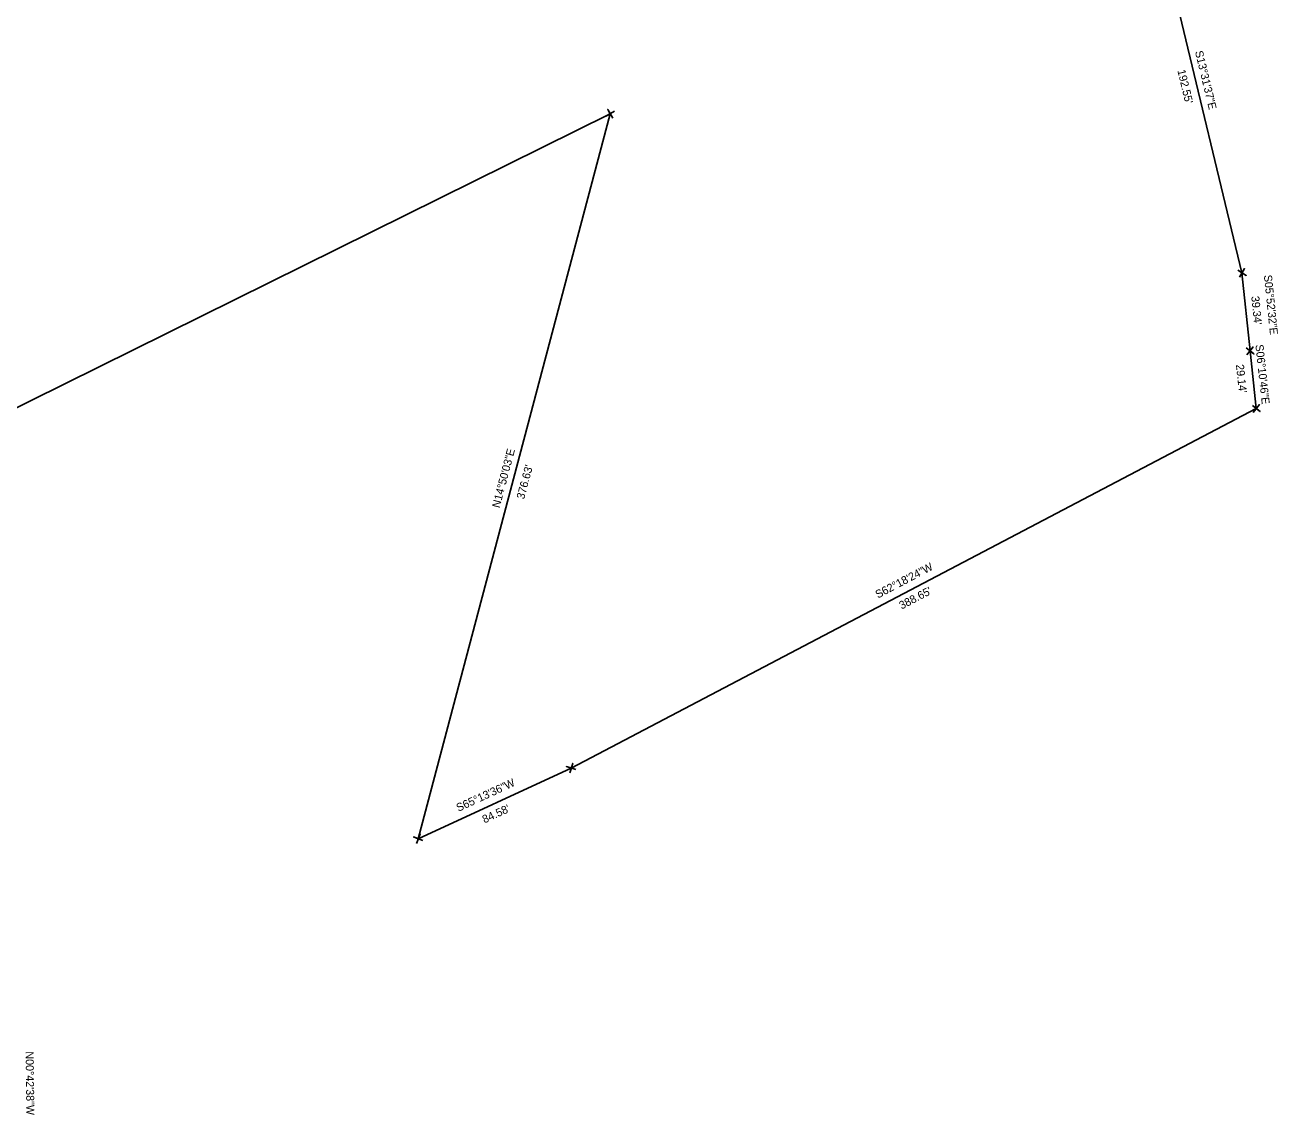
# Model space of a CAD drawing. Extents: x 1107874 to 1110849, y 645477 to 647181.
# Drawn here: x 1110220 to 1110849, y 646136 to 646683 of the extents above; entities that cross this region are included whole.
import ezdxf

# ---------------------------------------------------------------- set-up
doc = ezdxf.new("R2010")
doc.units = 0
for name, color, linetype in [('Exist Property Corner CELL', 7, 'Continuous'), ('Exist Property Line', 7, 'Continuous'), ('Exist Property Text', 7, 'Continuous')]:
    doc.layers.add(name, color=color, linetype=linetype)

msp = doc.modelspace()

# ---------------------------------------------------------------- linework, layer by layer
at = {"layer": 'Exist Property Corner CELL'}
for p, q in [((1110513.95, 646638.85), (1110513.95, 646638.85)), ((1110831.29, 646558.94), (1110831.29, 646558.94)), ((1110835.32, 646519.8), (1110835.32, 646519.8)), ((1110838.45, 646490.83), (1110838.45, 646490.83)), ((1110494.32, 646310.21), (1110494.32, 646310.21)), ((1110417.53, 646274.77), (1110417.53, 646274.77))]:
    msp.add_line(p, q, dxfattribs=at)
for points in [[(1110515.21, 646636.69), (1110512.7, 646641.01), (1110513.95, 646638.85), (1110511.79, 646637.59), (1110516.12, 646640.1)], [(1110829.16, 646560.24), (1110833.42, 646557.63), (1110831.29, 646558.94), (1110832.59, 646561.07), (1110829.98, 646556.8)], [(1110833.37, 646521.37), (1110837.26, 646518.23), (1110835.32, 646519.8), (1110836.88, 646521.75), (1110833.75, 646517.86)], [(1110836.51, 646492.4), (1110840.4, 646489.26), (1110838.45, 646490.83), (1110840.02, 646492.78), (1110836.88, 646488.88)], [(1110493.58, 646307.83), (1110495.07, 646312.6), (1110494.32, 646310.21), (1110491.94, 646310.96), (1110496.71, 646309.47)], [(1110416.66, 646272.43), (1110418.39, 646277.12), (1110417.53, 646274.77), (1110415.18, 646275.64), (1110419.87, 646273.91)]]:
    msp.add_lwpolyline(points, dxfattribs=at)
at = {"layer": 'Exist Property Line'}
for p, q in [((1110786.25, 646746.14), (1110831.29, 646558.94)), ((1110513.95, 646638.85), (1109853.98, 646312.24)), ((1110513.95, 646638.85), (1109882.58, 646326.39)), ((1110417.53, 646274.77), (1110513.95, 646638.85)), ((1110831.29, 646558.94), (1110835.32, 646519.8)), ((1110835.32, 646519.8), (1110838.45, 646490.83)), ((1110838.45, 646490.83), (1110494.32, 646310.21)), ((1110494.32, 646310.21), (1110417.53, 646274.77))]:
    msp.add_line(p, q, dxfattribs=at)

# ---------------------------------------------------------------- texts
at = {"layer": 'Exist Property Text'}
for s, rotation, p in [('S13°31\'37"E', 283.52686, (1110807.65, 646670.01)), ("192.55'", 283.52686, (1110798.81, 646660.58)), ('S05°52\'32"E', 275.87547, (1110842.29, 646557.77)), ("39.34'", 275.87547, (1110835.93, 646547.11)), ('S06°10\'46"E', 276.17936, (1110838.01, 646522.79)), ("29.14'", 276.17936, (1110828.23, 646512.82)), ('N14°50\'03"E', 75.16575, (1110458.34, 646440.6)), ("376.63'", 75.16575, (1110470.68, 646445.01)), ('S62°18\'24"W', 27.69324, (1110648.41, 646395.35)), ("388.65'", 27.69324, (1110660.34, 646389.82)), ('S65°13\'36"W', 24.77325, (1110437.71, 646288.25)), ("84.58'", 24.77325, (1110450.79, 646282.43)), ('N00°42\'38"W', 270.71059, (1110220.26, 646167.95))]:
    msp.add_text(s, height=4.02, rotation=rotation, dxfattribs=at).set_placement(p)

doc.saveas('drawing.dxf')
